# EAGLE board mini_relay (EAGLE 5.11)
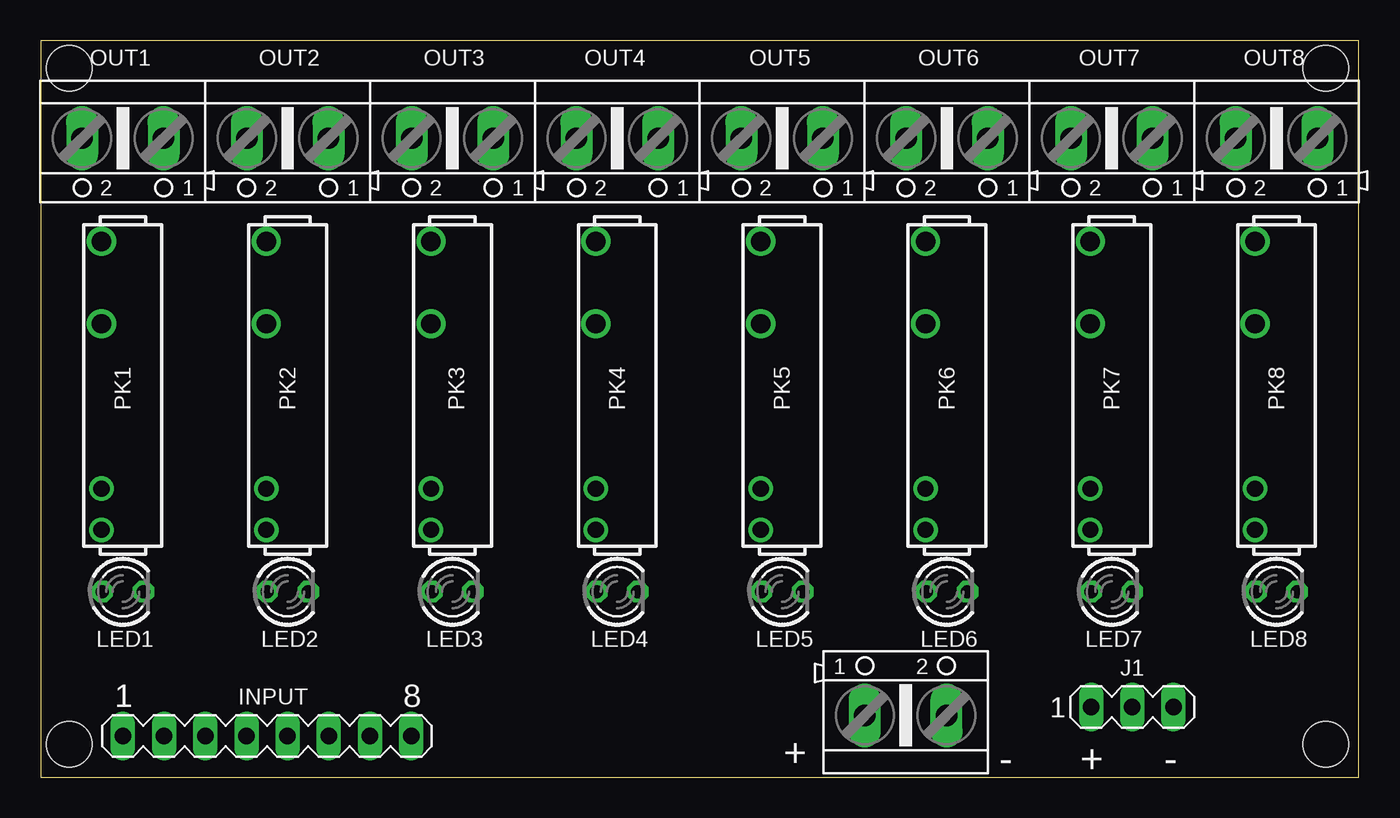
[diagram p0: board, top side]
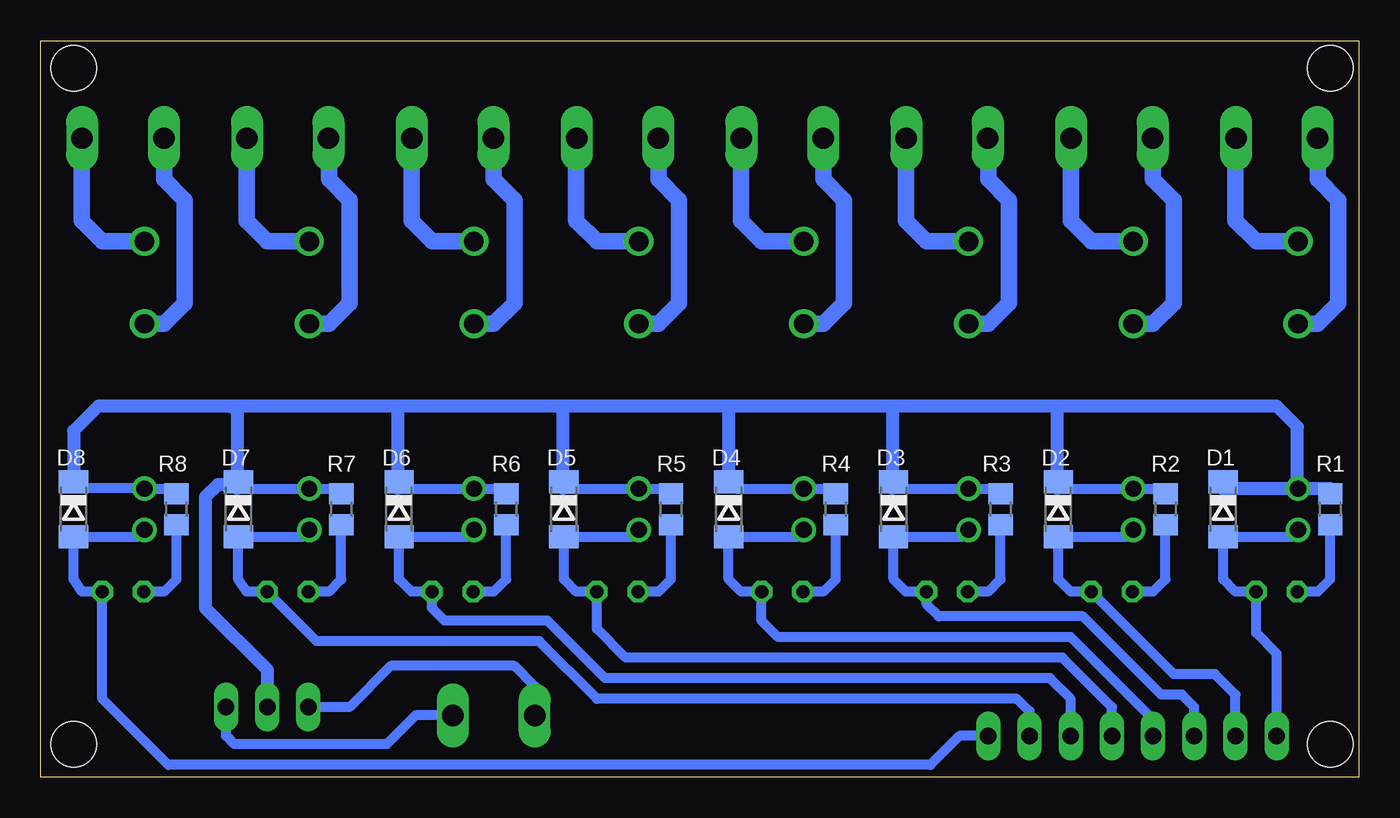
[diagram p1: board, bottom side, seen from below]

Size 81.27 x 45.39 mm. Coordinates in mm from the lower left corner, seen from the top.
Outline: 81.27,0 81.27,45.39 0,45.39 0,0 81.27,0
Copper layers (1*16): Top 0.035mm / dielectric 1.5mm / Bottom 0.035mm
Design rules "default": minimum track width 10mil, minimum drill 24mil, track to track 8mil, track to pad 8mil, pad to pad 8mil, via to via 8mil, smd to smd 8mil, copper to edge 40mil, drill to drill 8mil, minimum pad ring 10mil, minimum via ring 8mil, stop-mask expansion 4mil, vias tented up to drill 0mil, thermal gap 10mil
Holes 2.8 mm at 1.77,2.03 79.24,2.03 79.24,43.69 1.77,43.69

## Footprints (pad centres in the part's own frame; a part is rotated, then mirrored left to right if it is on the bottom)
AK500/2 = drill 1.321 long: 1 -2.515,0; 2 2.515,0
SOD80C = smd 1.4 x 1.8: A 1.7,0; C -1.7,0
MA08-1 = drill 1.016 long: 1 -8.89,0; 2 -6.35,0; 3 -3.81,0; 4 -1.27,0; 5 1.27,0; 6 3.81,0; 7 6.35,0; 8 8.89,0
MA03-1 = drill 1.016 long: 1 -2.54,0; 2 0,0; 3 2.54,0
LED3MM = drill 0.813 octagon: A -1.27,0; K 1.27,0
PA = drill 1 round: 1 -8.89,1.32; 2 -6.35,1.32 | drill 1.2 round: COM 8.89,1.32; NO 3.81,1.32
R0805 = smd 1.3 x 1.5: 1 -0.95,0; 2 0.95,0

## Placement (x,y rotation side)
+  [AK500/2]  53.33,3.81 0 top
D1  1N4148  [SOD80C]  8.37,16.51 270 bottom
D2  1N4148  [SOD80C]  18.53,16.51 270 bottom
D3  1N4148  [SOD80C]  28.69,16.51 270 bottom
D4  1N4148  [SOD80C]  38.85,16.51 270 bottom
D5  1N4148  [SOD80C]  49.01,16.51 270 bottom
D6  1N4148  [SOD80C]  59.17,16.51 270 bottom
D7  1N4148  [SOD80C]  69.08,16.51 270 bottom
D8  1N4148  [SOD80C]  79.24,16.51 270 bottom
INPUT  [MA08-1]  13.96,2.54 0 top
J1  [MA03-1]  67.3,4.32 0 top
LED1  [LED3MM]  5.07,11.43 0 top
LED2  [LED3MM]  15.23,11.43 0 top
LED3  [LED3MM]  25.39,11.43 0 top
LED4  [LED3MM]  35.55,11.43 0 top
LED5  [LED3MM]  45.71,11.43 0 top
LED6  [LED3MM]  55.87,11.43 0 top
LED7  [LED3MM]  66.03,11.43 0 top
LED8  [LED3MM]  76.19,11.43 0 top
OUT1  [AK500/2]  5.07,39.37 180 top
OUT2  [AK500/2]  15.23,39.37 180 top
OUT3  [AK500/2]  25.39,39.37 180 top
OUT4  [AK500/2]  35.55,39.37 180 top
OUT5  [AK500/2]  45.71,39.37 180 top
OUT6  [AK500/2]  55.87,39.37 180 top
OUT7  [AK500/2]  66.03,39.37 180 top
OUT8  [AK500/2]  76.19,39.37 180 top
PK1  PA1A-12V  [PA]  5.07,24.13 90 top
PK2  PA1A-12V  [PA]  15.23,24.13 90 top
PK3  PA1A-12V  [PA]  25.39,24.13 90 top
PK4  PA1A-12V  [PA]  35.55,24.13 90 top
PK5  PA1A-12V  [PA]  45.71,24.13 90 top
PK6  PA1A-12V  [PA]  55.87,24.13 90 top
PK7  PA1A-12V  [PA]  66.03,24.13 90 top
PK8  PA1A-12V  [PA]  76.19,24.13 90 top
R1  [R0805]  1.77,16.51 90 bottom
R2  [R0805]  11.93,16.51 90 bottom
R3  [R0805]  22.09,16.51 90 bottom
R4  [R0805]  32.25,16.51 90 bottom
R5  [R0805]  42.41,16.51 90 bottom
R6  [R0805]  52.57,16.51 90 bottom
R7  [R0805]  62.73,16.51 90 bottom
R8  [R0805]  72.89,16.51 90 bottom

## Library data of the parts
+ OUT1-OUT8 = con-ptr500; OC_FARNELL: unknown; OC_NEWARK: unknown
D1-D8 = diode
INPUT J1 = con-lstb; OC_FARNELL: unknown; OC_NEWARK: unknown
LED1-LED8 = led
PK1-PK8 = relay; MF: AROMAT/ MATSUSHITA; MPN: PA1A-12V-Y1; OC_FARNELL: 910363; OC_NEWARK: 82H8374
R1-R8 = rcl

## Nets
N$1: OUT1.2 PK1.NO
N$2: OUT1.1 PK1.COM
N$3: D1.A INPUT.1 LED1.K PK1.1
N$4: D1.C D2.C D3.C D4.C D5.C D6.C D7.C D8.C J1.2 PK1.2 PK2.2 PK3.2 PK4.2 PK5.2 PK6.2 PK7.2 PK8.2 R1.2 R2.2 R3.2 R4.2 R5.2 R6.2 R7.2 R8.2
N$5: LED1.A R1.1
N$6: OUT2.2 PK2.NO
N$7: OUT2.1 PK2.COM
N$8: D2.A INPUT.2 LED2.K PK2.1
N$9: +.1 J1.1
N$10: LED2.A R2.1
N$11: OUT3.2 PK3.NO
N$12: OUT3.1 PK3.COM
N$13: D3.A INPUT.3 LED3.K PK3.1
N$14: +.2 J1.3
N$15: LED3.A R3.1
N$16: OUT4.2 PK4.NO
N$17: OUT4.1 PK4.COM
N$18: D4.A INPUT.4 LED4.K PK4.1
N$19: LED4.A R4.1
N$20: LED5.A R5.1
N$21: OUT5.2 PK5.NO
N$22: OUT5.1 PK5.COM
N$23: D5.A INPUT.5 LED5.K PK5.1
N$24: LED6.A R6.1
N$25: LED7.A R7.1
N$26: OUT6.2 PK6.NO
N$27: OUT6.1 PK6.COM
N$28: D6.A INPUT.6 LED6.K PK6.1
N$29: LED8.A R8.1
N$31: OUT7.2 PK7.NO
N$32: OUT7.1 PK7.COM
N$36: OUT8.2 PK8.NO
N$37: OUT8.1 PK8.COM
N$45: D7.A INPUT.7 LED7.K PK7.1
N$46: D8.A INPUT.8 LED8.K PK8.1

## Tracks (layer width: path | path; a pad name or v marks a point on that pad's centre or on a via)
N$1
  Bottom 1.016: PK1.NO 2.53,27.94 1.26,29.21 1.26,35.56 2.53,36.83 2.53,39.34 OUT1.2
N$2
  Bottom 1.016: PK1.COM 6.34,33.02 7.61,34.29 7.61,39.34 OUT1.1
N$3
  Bottom 0.61: PK1.1 4.18,14.81 D1.A 8.37,12.19 7.61,11.43 LED1.K 6.34,8.89 5.07,7.62 INPUT.1
N$4
  Bottom 0.61: D8.C 79.62,17.83 74.92,17.83 PK8.2 72.7,17.78 R8.2 | D7.C 69.16,17.78 PK7.2 62.54,17.78 R7.2 | D6.C 59.25,17.78 PK6.2 52.38,17.78 R6.2 | D5.C 49.09,17.78 PK5.2 42.22,17.78 R5.2 | 32.76,17.78 32.06,17.78 R4.2 32.44,17.46 32.76,17.78 | 32.76,17.78 PK4.2 38.42,17.78 D4.C | D3.C 28.77,17.78 PK3.2 21.9,17.78 R3.2 | D2.C 18.61,17.78 PK2.2 11.74,17.78 R2.2 | PK1.2 3.8,17.78 | 8.45,17.78 D1.C
  Bottom 0.813: PK1.2 1.77,17.78 R1.2 | 8.45,17.78 3.8,17.78 3.8,21.59 5.07,22.86 18.79,22.86 | 18.79,22.86 28.69,22.86 | 28.69,22.86 28.95,22.86 | 28.95,22.86 39.11,22.86 | 39.11,22.86 49.01,22.86 | 49.01,22.86 59.43,22.86 | 59.43,22.86 69.59,22.86 | 69.59,22.86 77.71,22.86 79.24,21.34 D8.C | 69.16,17.78 69.16,22.68 69.59,22.86 | 59.25,17.78 59.25,22.68 59.43,22.86 | J1.2 67.3,6.6 71.11,10.41 71.11,17.27 70.35,18.03 69.25,18.03 D7.C | 49.09,17.78 49.09,22.78 49.01,22.86 | D4.C 38.85,22.61 39.11,22.86 | 28.77,22.68 28.77,17.78 | 28.95,22.86 28.77,22.68 | 18.61,17.78 18.61,22.68 18.79,22.86 | 28.77,22.68 28.77,22.78 28.69,22.86
N$5
  Bottom 0.61: R1.1 1.77,12.19 2.53,11.43 LED1.A
N$6
  Bottom 1.016: PK2.NO 12.69,27.94 11.42,29.21 11.42,35.56 12.69,36.83 12.69,39.34 OUT2.2
N$7
  Bottom 1.016: PK2.COM 16.5,33.02 17.77,34.29 17.77,39.34 OUT2.1
N$8
  Bottom 0.61: INPUT.2 7.61,5.08 8.88,6.35 11.42,6.35 LED2.K 17.77,11.43 18.53,12.19 D2.A 14.34,14.81 PK2.1
N$9
  Bottom 0.61: +.1 50.81,5.61 52.06,6.86 59.68,6.86 62.22,4.32 J1.1
N$10
  Bottom 0.61: R2.1 11.93,12.19 12.69,11.43 LED2.A
N$11
  Bottom 1.016: PK3.NO 22.85,27.94 21.58,29.21 21.58,35.56 22.85,36.83 22.85,39.34 OUT3.2
N$12
  Bottom 1.016: PK3.COM 26.66,33.02 27.93,34.29 27.93,39.34 OUT3.1
N$13
  Bottom 0.61: PK3.1 24.5,14.81 D3.A 28.69,12.19 27.93,11.43 LED3.K 26.66,10.67 25.9,9.91 17.01,9.91 12.18,5.08 10.91,5.08 10.15,4.32 INPUT.3
N$14
  Bottom 0.61: J1.3 69.84,2.54 69.33,2.03 59.93,2.03 58.16,3.81 +.2
N$15
  Bottom 0.61: R3.1 22.09,12.19 22.85,11.43 LED3.A
N$16
  Bottom 1.016: PK4.NO 33.01,27.94 31.74,29.21 31.74,35.56 33.01,36.83 33.01,39.34 OUT4.2
N$17
  Bottom 1.016: PK4.COM 36.82,33.02 38.09,34.29 38.09,39.34 OUT4.1
N$18
  Bottom 0.61: PK4.1 34.66,14.81 D4.A 38.85,12.19 38.09,11.43 LED4.K 36.82,9.65 35.8,8.64 17.77,8.64 12.69,3.56 INPUT.4
N$19
  Bottom 0.61: R4.1 32.25,12.19 33.01,11.43 LED4.A
N$20
  Bottom 0.61: R5.1 42.41,12.19 43.17,11.43 LED5.A
N$21
  Bottom 1.016: PK5.NO 43.17,27.94 41.9,29.21 41.9,35.56 43.17,36.83 43.17,39.34 OUT5.2
N$22
  Bottom 1.016: PK5.COM 46.98,33.02 48.25,34.29 48.25,39.34 OUT5.1
N$23
  Bottom 0.61: PK5.1 44.44,15.24 44.87,14.81 D5.A 49.01,12.19 48.25,11.43 LED5.K 46.98,9.14 45.2,7.37 18.28,7.37 15.23,4.32 INPUT.5
N$24
  Bottom 0.61: R6.1 52.57,12.19 53.33,11.43 LED6.A
N$25
  Bottom 0.61: R7.1 62.73,12.19 63.49,11.43 LED7.A
N$26
  Bottom 1.016: PK6.NO 53.33,27.94 52.06,29.21 52.06,35.56 53.33,36.83 53.33,39.34 OUT6.2
N$27
  Bottom 1.016: PK6.COM 57.14,33.02 58.41,34.29 58.41,39.34 OUT6.1
N$28
  Bottom 0.61: PK6.1 54.98,14.81 D6.A 59.17,12.19 58.41,11.43 LED6.K 57.14,10.41 56.38,9.65 50.03,9.65 46.47,6.1 19.04,6.1 17.77,4.83 INPUT.6
N$29
  Bottom 0.61: R8.1 72.89,12.19 73.65,11.43 LED8.A
N$31
  Bottom 1.016: PK7.NO 63.49,27.94 62.22,29.21 62.22,35.56 63.49,36.83 63.49,39.34 OUT7.2
N$32
  Bottom 1.016: PK7.COM 67.3,33.02 68.57,34.29 68.57,39.34 OUT7.1
N$36
  Bottom 1.016: PK8.NO 73.65,27.94 72.38,29.21 72.38,35.56 73.65,36.83 73.65,39.34 OUT8.2
N$37
  Bottom 1.016: PK8.COM 77.46,33.02 78.73,34.29 78.73,39.34 OUT8.1
N$45
  Bottom 0.61: PK7.1 65.14,14.81 D7.A 69.08,12.19 68.57,11.43 LED7.K 64.25,8.38 50.54,8.38 46.98,4.83 21.07,4.83 20.31,4.06 INPUT.7
N$46
  Bottom 0.61: PK8.1 75.3,14.81 D8.A 79.24,12.19 78.73,11.43 LED8.K 77.46,4.83 73.4,0.76 26.41,0.76 24.63,2.54 INPUT.8

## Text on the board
tNames: 1 | 8 | - | + | -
